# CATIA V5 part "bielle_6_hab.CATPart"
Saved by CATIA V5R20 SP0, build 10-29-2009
Part number: bielle_6_hab
Bounding box of the stored display mesh (mm): x 0.05 to 0.1, y 1.97 to 2.18, z 1.07 to 2.27
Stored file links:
  D:\Dropbox\IAO_2012\IAO_2012_718_ccascaro\ccascaro\bielle_6_hab.CATPart
  C:\Users\Cédric\Documents\IFMA-2A\IAO\Projet IAO\Projet IAO catia\ass_bielles_skl.CATProduct
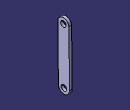
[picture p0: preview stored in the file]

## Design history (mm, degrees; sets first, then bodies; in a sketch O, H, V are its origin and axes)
Set1
  Point1 "point B": linked copy from another document
  Point2 "point G": linked copy from another document
Body1 (main body)
  Sketch1 on yz-plane, origin (0, 0, 0), H (0, 1, 0), V (0, 0, 1)
    construction line L1 (2.07, 2.17) -> (2.08, 1.17)
    point P1 (2.07, 2.17)
    point P2 (2.08, 1.17)
    line L2 (2.17, 2.171) -> (2.18, 1.171)
    line L3 (1.98, 1.169) -> (1.97, 2.169)
    arc A1 centre (2.08, 1.17) radius 0.1 from (2.18, 1.171) to (1.98, 1.169) cw
    arc A2 centre (2.07, 2.17) radius 0.1 from (1.97, 2.169) to (2.17, 2.171) cw
    circle A3 centre (2.07, 2.17) radius 0.05
    point P7 (2.0705, 2.12)
    circle A4 centre (2.08, 1.17) radius 0.05
    reference projected point E1 (2.07, 2.17) from Point1
    reference projected point E2 (2.08, 1.17) from Point2
    distance L1 L2 = 0.1
    distance E1 P1 = 0
    distance P2 E2 = 0
    tangency: A1 L2, A2 L2, A1 L3, A2 L3
    coincidence: A3 P7, P7 L1
  Pad1: profile Sketch1, direction (1, 0, 0), length 0.05, opposite side length -0.1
